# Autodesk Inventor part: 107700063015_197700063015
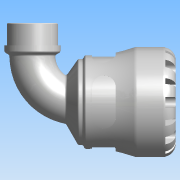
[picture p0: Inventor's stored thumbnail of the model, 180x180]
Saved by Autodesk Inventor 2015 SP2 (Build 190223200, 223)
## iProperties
Created: 2016-12
Part Number: 107700063015_197700063015
Material: PVC-Piping
Description: PLASSON 90° ELBOW WITH MALE INTEGRAL BRASS 63X1.1/2" SERIES 1
Document SubType Name: Modeling
Designer: KIM
Mass: 664.223 g
Surface Area: 733.008 cm^2
Volume: 474.445 cm^3
Density: 1.4 g/cm^3
Appearance: Smooth - White
Author: KIM
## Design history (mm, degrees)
derived "1077.ipt"
feature "Solid1::1077.ipt"
tag "TaggingFeature1"
body "Solid1"
other parameters: "d1" = 37.8, "d2" = 63, "d3" = 78.75, "d4" = 103, "d8" = 87.55, "d13" = 9.7, "d14" = 9.7, "d15" = 0, "d17" = 360 deg, "d19" = 8 deg, "d20" = 1.26, "d21" = 1.26, "d22" = 8 deg, "d24" = 0, "d26" = 360 deg, "d33" = 10.3, "d43" = 80.34, "d51" = 1.03, "d54" = 22.05, "d55" = 13.86, "d57" = 19.012, "d58" = 0, "d74" = 0, "d82" = 1.26, "d115" = 360 deg, "d207" = 90 deg, "d228" = 18.7425, "d247" = 2.06, "d248" = 5.4, "d268" = 48.1525, "d269" = 5.4, "d270" = 134, "d276" = 47.803, "d277" = 21, "d278" = 52.5833, "d279" = 74, "d280" = 27.3, "d281" = 7.17045, "d283" = 43.0227, "d286" = 0, "d287" = 0, "d288" = 33.4621, "d290" = 18.65865, "d292" = 30 deg, "d294" = 4.7803, "d296" = 30 deg, "d_" = 63, "E_" = 103, "A_" = 134, "A_1" = 74, "l_2" = 21, "R_" = 47.803, "d9" = 12.125, "d11" = 103, "d12" = 78.75, "d289" = 33.4621
